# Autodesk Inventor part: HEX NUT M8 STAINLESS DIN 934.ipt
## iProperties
Created: 2006-02
Part Number: HEX NUT M8 STAINLESS DIN 934.ipt
Material: Stainless Steel, Austenitic
Description: Hex Nut
Document SubType Name: Modeling
Standard: DIN 934
Designer: Andy Moles
Standards Organization: DIN
Language: en-US
Size Designation: M8
Categories: <MemberInstance><Categories><Category DisplayName="Fasteners" InternalName="e4da775c-781d-43d5-af7c-5136215cf5a6" Mnemonic="FSTN"><Category DisplayName="Nuts" I
Mass: 5.50403 g
Surface Area: 5.92403 cm^2
Volume: 0.685433 cm^3
Density: 8.03 g/cm^3
Author: Andy Moles
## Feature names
1. Body [Extrusion]
2. Chamfer1 [Revolution]
3. Thread [Hole]
4. Chamfer2
5. Chamfer3
